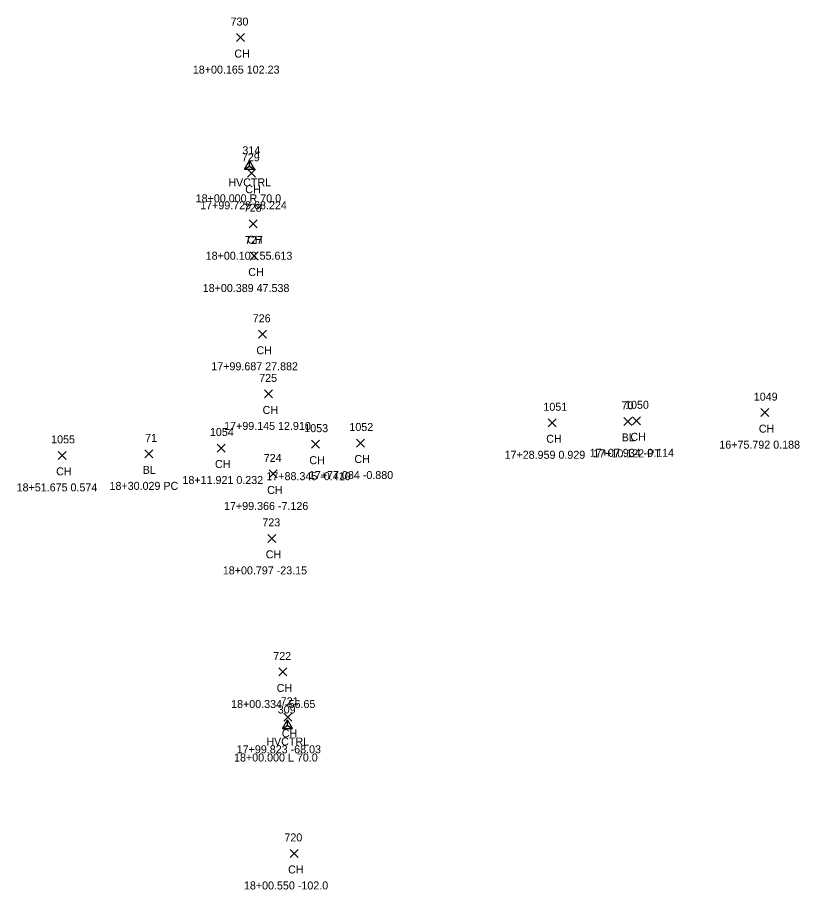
# Model space of a CAD drawing. Extents: x 89316 to 92454, y 84175 to 86051.
# Drawn here: x 90500.9 to 90696.2, y 85062.9 to 85280.8 of the extents above; entities that cross this region are included whole.
import ezdxf

# ---------------------------------------------------------------- set-up
doc = ezdxf.new("R2010")
doc.units = 0
for name, color, linetype in [('C_A', 7, 'Continuous'), ('C_C', 7, 'Continuous'), ('C_I', 7, 'Continuous'), ('C_TIC', 7, 'Continuous'), ('CPSM', 7, 'Continuous'), ('L_A', 7, 'Continuous'), ('L_C', 7, 'Continuous'), ('L_I', 7, 'Continuous'), ('L_TIC', 7, 'Continuous')]:
    doc.layers.add(name, color=color, linetype=linetype)

msp = doc.modelspace()

# ---------------------------------------------------------------- linework, layer by layer
at = {"layer": 'C_TIC'}
for points in [[(90652.34, 85178.91), (90654.34, 85180.91)], [(90654.34, 85178.91), (90652.34, 85180.91)], [(90532.71, 85170.79), (90534.71, 85172.79)], [(90534.71, 85170.79), (90532.71, 85172.79)]]:
    msp.add_lwpolyline(points, dxfattribs=at)
at = {"layer": 'CPSM'}
for p, q in [((90557.64, 85242.92), (90558.89, 85245.08)), ((90560.14, 85242.92), (90558.89, 85245.08)), ((90558.89, 85243.64), (90558.89, 85245.08)), ((90557.64, 85242.92), (90558.89, 85243.64)), ((90557.64, 85242.92), (90560.14, 85242.92)), ((90558.89, 85243.64), (90558.89, 85243.64)), ((90558.89, 85243.64), (90560.14, 85242.92)), ((90567.12, 85103.18), (90568.37, 85105.35)), ((90569.62, 85103.18), (90568.37, 85105.35)), ((90568.37, 85103.91), (90568.37, 85105.35)), ((90567.12, 85103.18), (90568.37, 85103.91)), ((90567.12, 85103.18), (90569.62, 85103.18)), ((90568.37, 85103.91), (90568.37, 85103.91)), ((90568.37, 85103.91), (90569.62, 85103.18))]:
    msp.add_line(p, q, dxfattribs=at)
at = {"layer": 'L_TIC'}
for points in [[(90555.59, 85274.81), (90557.59, 85276.81)], [(90557.59, 85274.81), (90555.59, 85276.81)], [(90558.33, 85240.91), (90560.33, 85242.91)], [(90560.33, 85240.91), (90558.33, 85242.91)], [(90558.81, 85228.3), (90560.81, 85230.3)], [(90560.81, 85228.3), (90558.81, 85230.3)], [(90559.07, 85220.23), (90561.07, 85222.23)], [(90561.07, 85220.23), (90559.07, 85222.23)], [(90561.1, 85200.67), (90563.1, 85202.67)], [(90563.1, 85200.67), (90561.1, 85202.67)], [(90562.65, 85185.76), (90564.65, 85187.76)], [(90564.65, 85185.76), (90562.65, 85187.76)], [(90686.6, 85181.09), (90688.6, 85183.09)], [(90688.6, 85181.09), (90686.6, 85183.09)], [(90633.49, 85178.56), (90635.49, 85180.56)], [(90635.49, 85178.56), (90633.49, 85180.56)], [(90654.53, 85179.05), (90656.53, 85181.05)], [(90656.53, 85179.05), (90654.53, 85181.05)], [(90574.33, 85173.21), (90576.33, 85175.21)], [(90576.33, 85173.21), (90574.33, 85175.21)], [(90585.6, 85173.5), (90587.6, 85175.5)], [(90587.6, 85173.5), (90585.6, 85175.5)], [(90550.76, 85172.25), (90552.76, 85174.25)], [(90552.76, 85172.25), (90550.76, 85174.25)], [(90511.1, 85170.41), (90513.1, 85172.41)], [(90513.1, 85170.41), (90511.1, 85172.41)], [(90563.79, 85165.76), (90565.79, 85167.76)], [(90565.79, 85165.76), (90563.79, 85167.76)], [(90563.45, 85149.67), (90565.45, 85151.67)], [(90565.45, 85149.67), (90563.45, 85151.67)], [(90566.17, 85116.28), (90568.17, 85118.28)], [(90568.17, 85116.28), (90566.17, 85118.28)], [(90567.45, 85104.96), (90569.45, 85106.96)], [(90569.45, 85104.96), (90567.45, 85106.96)], [(90569.03, 85070.94), (90571.03, 85072.94)], [(90571.03, 85070.94), (90569.03, 85072.94)]]:
    msp.add_lwpolyline(points, dxfattribs=at)

# ---------------------------------------------------------------- texts
at = {"layer": 'C_A'}
for s, p in [('HVCTRL', (90553.58, 85238.64)), ('BL', (90651.83, 85174.91)), ('BL', (90532.2, 85166.79)), ('HVCTRL', (90563.07, 85098.91))]:
    msp.add_text(s, height=2, dxfattribs=at).set_placement(p)
at = {"layer": 'C_C'}
for s, p in [('18+00.000 R 70.0', (90545.43, 85234.64)), ('17+10.122 PT', (90644.72, 85170.91)), ('18+30.029 PC', (90523.91, 85162.79)), ('18+00.000 L 70.0', (90555.01, 85094.91))]:
    msp.add_text(s, height=2, dxfattribs=at).set_placement(p)
at = {"layer": 'C_I'}
for s, p in [('314', (90557.09, 85246.64)), ('70', (90651.79, 85182.91)), ('71', (90532.81, 85174.79)), ('309', (90565.93, 85106.91))]:
    msp.add_text(s, height=2, dxfattribs=at).set_placement(p)
at = {"layer": 'L_A'}
for p in [(90555.08, 85270.81), (90557.81, 85236.91), (90558.29, 85224.3), (90558.56, 85216.23), (90560.59, 85196.67), (90562.14, 85181.76), (90686.08, 85177.09), (90654.02, 85175.05), (90632.98, 85174.56), (90573.82, 85169.21), (90585.08, 85169.5), (90510.59, 85166.41), (90550.25, 85168.25), (90563.28, 85161.76), (90562.93, 85145.67), (90565.66, 85112.28), (90566.94, 85100.96), (90568.52, 85066.94)]:
    msp.add_text('CH', height=2, dxfattribs=at).set_placement(p)
at = {"layer": 'L_C'}
for s, p in [('18+00.165 102.23', (90544.72, 85266.81)), ('17+99.729 68.224', (90546.55, 85232.91)), ('18+00.103 55.613', (90547.93, 85220.3)), ('18+00.389 47.538', (90547.19, 85212.23)), ('17+99.687 27.882', (90549.33, 85192.67)), ('17+99.145 12.910', (90552.54, 85177.76)), ('16+75.792 0.188', (90676.21, 85173.09)), ('17+28.959 0.929', (90622.57, 85170.56)), ('17+07.934 -0.114', (90643.86, 85171.05)), ('18+11.921 0.232', (90542.13, 85164.25)), ('17+88.345 -0.410', (90563.09, 85165.21)), ('17+77.084 -0.880', (90573.71, 85165.5)), ('18+51.675 0.574', (90500.71, 85162.41)), ('17+99.366 -7.126', (90552.51, 85157.76)), ('18+00.797 -23.15', (90552.21, 85141.67)), ('18+00.334 -56.65', (90554.28, 85108.28)), ('17+99.823 -68.03', (90555.68, 85096.96)), ('18+00.550 -102.0', (90557.48, 85062.94))]:
    msp.add_text(s, height=2, dxfattribs=at).set_placement(p)
at = {"layer": 'L_I'}
for s, p in [('730', (90554.14, 85278.81)), ('729', (90556.96, 85244.91)), ('728', (90557.44, 85232.3)), ('727', (90557.71, 85224.23)), ('726', (90559.68, 85204.67)), ('725', (90561.29, 85189.76)), ('1049', (90684.82, 85185.09)), ('1051', (90632.28, 85182.56)), ('1050', (90652.67, 85183.05)), ('1053', (90572.56, 85177.21)), ('1052', (90583.82, 85177.5)), ('1054', (90548.99, 85176.25)), ('1055', (90509.33, 85174.41)), ('724', (90562.43, 85169.76)), ('723', (90562.08, 85153.67)), ('722', (90564.81, 85120.28)), ('721', (90566.66, 85108.96)), ('720', (90567.59, 85074.94))]:
    msp.add_text(s, height=2, dxfattribs=at).set_placement(p)

doc.saveas('drawing.dxf')
